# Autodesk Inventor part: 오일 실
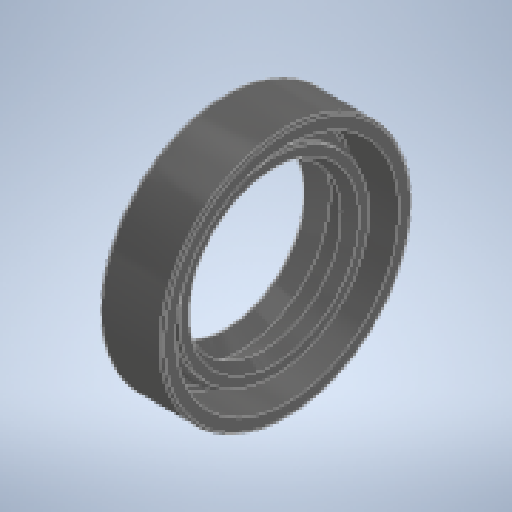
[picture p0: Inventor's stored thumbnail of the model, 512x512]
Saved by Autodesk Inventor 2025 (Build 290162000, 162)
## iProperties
Created: 2024-08
Part Number: 오일 실
Material: 고무
Description: 오일-실
Document SubType Name: Modeling
Designer: Administrator
Density: 0.93 g/cm^3
Appearance: 기본값
Author: jhkim
Sending System: Autodesk Inventor 2025
Preprocessor: ST-DEVELOPER v20
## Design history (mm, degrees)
feature "Solid1"
node "솔리드1"
